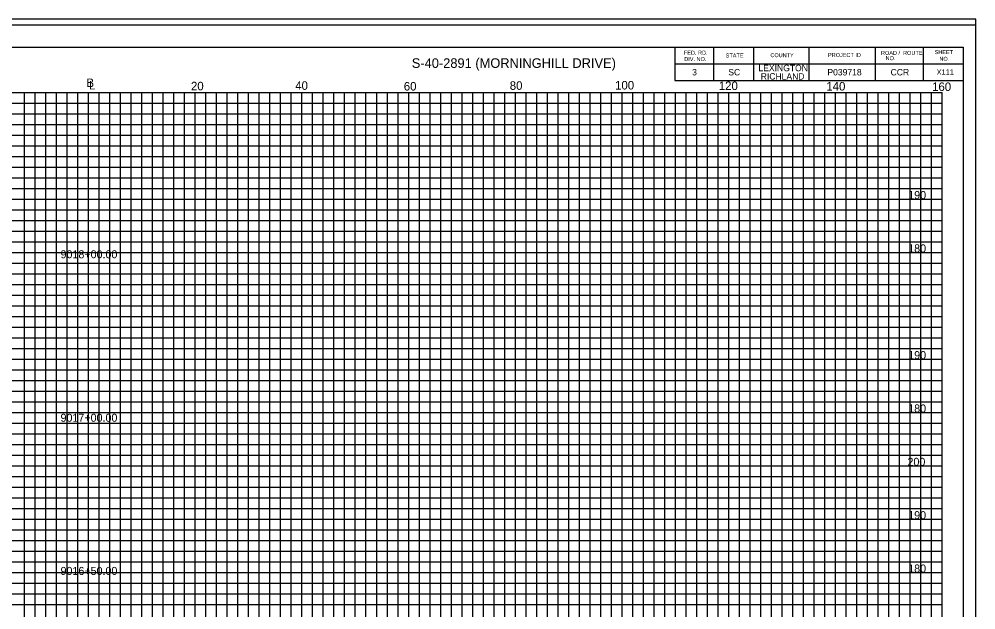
# Model space of a CAD drawing. Extents: x 967 to 1326, y 964 to 2584.
# Drawn here: x 1147 to 1326.3, y 2193 to 2303.7 of the extents above; entities that cross this region are included whole.
import ezdxf

# ---------------------------------------------------------------- set-up
doc = ezdxf.new("R2010")
doc.units = 0
for name, color, linetype in [('Default', 7, 'Continuous'), ('RD_GPK_XS_Cell', 7, 'Continuous'), ('RD_XS_ExGround', 7, 'Continuous'), ('RD_XS_ExPaveRet', 7, 'Continuous'), ('RD_XS_Misc_Line', 7, 'Continuous'), ('RD_XS_TX_Elev_EX', 7, 'Continuous')]:
    doc.layers.add(name, color=color, linetype=linetype)

msp = doc.modelspace()

# ---------------------------------------------------------------- linework, layer by layer
at = {"layer": 'RD_GPK_XS_Cell'}
for p, q in [((1000, 2290), (1320, 2290)), ((1150, 2120), (1150, 2290)), ((1160, 2120), (1160, 2290)), ((1170, 2120), (1170, 2290)), ((1180, 2120), (1180, 2290)), ((1190, 2120), (1190, 2290)), ((1200, 2120), (1200, 2290)), ((1210, 2120), (1210, 2290)), ((1220, 2120), (1220, 2290)), ((1230, 2120), (1230, 2290)), ((1240, 2120), (1240, 2290)), ((1250, 2120), (1250, 2290)), ((1260, 2120), (1260, 2290)), ((1270, 2120), (1270, 2290)), ((1280, 2120), (1280, 2290)), ((1290, 2120), (1290, 2290)), ((1300, 2120), (1300, 2290)), ((1310, 2120), (1310, 2290)), ((1320, 2120), (1320, 2290)), ((1000, 2280), (1320, 2280)), ((1000, 2270), (1320, 2270)), ((1000, 2260), (1320, 2260)), ((1000, 2250), (1320, 2250)), ((1000, 2240), (1320, 2240)), ((1000, 2230), (1320, 2230)), ((1000, 2220), (1320, 2220)), ((1000, 2210), (1320, 2210)), ((1000, 2200), (1320, 2200))]:
    msp.add_line(p, q, dxfattribs=at)
at = {"layer": 'RD_XS_ExGround'}
for p, q in [((1148, 2120), (1148, 2290)), ((1152, 2120), (1152, 2290)), ((1154, 2120), (1154, 2290)), ((1156, 2120), (1156, 2290)), ((1158, 2120), (1158, 2290)), ((1162, 2120), (1162, 2290)), ((1164, 2120), (1164, 2290)), ((1166, 2120), (1166, 2290)), ((1168, 2120), (1168, 2290)), ((1172, 2120), (1172, 2290)), ((1174, 2120), (1174, 2290)), ((1176, 2120), (1176, 2290)), ((1178, 2120), (1178, 2290)), ((1182, 2120), (1182, 2290)), ((1184, 2120), (1184, 2290)), ((1186, 2120), (1186, 2290)), ((1188, 2120), (1188, 2290)), ((1192, 2120), (1192, 2290)), ((1194, 2120), (1194, 2290)), ((1196, 2120), (1196, 2290)), ((1198, 2120), (1198, 2290)), ((1202, 2120), (1202, 2290)), ((1204, 2120), (1204, 2290)), ((1206, 2120), (1206, 2290)), ((1208, 2120), (1208, 2290)), ((1212, 2120), (1212, 2290)), ((1214, 2120), (1214, 2290)), ((1216, 2120), (1216, 2290)), ((1218, 2120), (1218, 2290)), ((1222, 2120), (1222, 2290)), ((1224, 2120), (1224, 2290)), ((1226, 2120), (1226, 2290)), ((1228, 2120), (1228, 2290)), ((1232, 2120), (1232, 2290)), ((1234, 2120), (1234, 2290)), ((1236, 2120), (1236, 2290)), ((1238, 2120), (1238, 2290)), ((1242, 2120), (1242, 2290)), ((1244, 2120), (1244, 2290)), ((1246, 2120), (1246, 2290)), ((1248, 2120), (1248, 2290)), ((1252, 2120), (1252, 2290)), ((1254, 2120), (1254, 2290)), ((1256, 2120), (1256, 2290)), ((1258, 2120), (1258, 2290)), ((1262, 2120), (1262, 2290)), ((1264, 2120), (1264, 2290)), ((1266, 2120), (1266, 2290)), ((1268, 2120), (1268, 2290)), ((1272, 2120), (1272, 2290)), ((1274, 2120), (1274, 2290)), ((1276, 2120), (1276, 2290)), ((1278, 2120), (1278, 2290)), ((1282, 2120), (1282, 2290)), ((1284, 2120), (1284, 2290)), ((1286, 2120), (1286, 2290)), ((1288, 2120), (1288, 2290)), ((1292, 2120), (1292, 2290)), ((1294, 2120), (1294, 2290)), ((1296, 2120), (1296, 2290)), ((1298, 2120), (1298, 2290)), ((1302, 2120), (1302, 2290)), ((1304, 2120), (1304, 2290)), ((1306, 2120), (1306, 2290)), ((1308, 2120), (1308, 2290)), ((1312, 2120), (1312, 2290)), ((1314, 2120), (1314, 2290)), ((1316, 2120), (1316, 2290)), ((1318, 2120), (1318, 2290)), ((1000, 2288), (1320, 2288)), ((1000, 2286), (1320, 2286)), ((1000, 2284), (1320, 2284)), ((1000, 2282), (1320, 2282)), ((1000, 2278), (1320, 2278)), ((1000, 2276), (1320, 2276)), ((1000, 2274), (1320, 2274)), ((1000, 2272), (1320, 2272)), ((1000, 2268), (1320, 2268)), ((1000, 2266), (1320, 2266)), ((1000, 2264), (1320, 2264)), ((1000, 2262), (1320, 2262)), ((1000, 2258), (1320, 2258)), ((1000, 2256), (1320, 2256)), ((1000, 2254), (1320, 2254)), ((1000, 2252), (1320, 2252)), ((1000, 2248), (1320, 2248)), ((1000, 2246), (1320, 2246)), ((1000, 2244), (1320, 2244)), ((1000, 2242), (1320, 2242)), ((1000, 2238), (1320, 2238)), ((1000, 2236), (1320, 2236)), ((1000, 2234), (1320, 2234)), ((1000, 2232), (1320, 2232)), ((1000, 2228), (1320, 2228)), ((1000, 2226), (1320, 2226)), ((1000, 2224), (1320, 2224)), ((1000, 2222), (1320, 2222)), ((1000, 2218), (1320, 2218)), ((1000, 2216), (1320, 2216)), ((1000, 2214), (1320, 2214)), ((1000, 2212), (1320, 2212)), ((1000, 2208), (1320, 2208)), ((1000, 2206), (1320, 2206)), ((1000, 2204), (1320, 2204)), ((1000, 2202), (1320, 2202)), ((1000, 2198), (1320, 2198)), ((1000, 2196), (1320, 2196)), ((1000, 2194), (1320, 2194))]:
    msp.add_line(p, q, dxfattribs=at)
at = {"layer": 'RD_XS_ExPaveRet'}
for points in [[(967.41, 2083.72), (1326.28, 2083.72), (1326.28, 2303.72), (967.41, 2303.72)], [(988.52, 2084.84), (1326.28, 2084.84), (1326.28, 2302.6), (988.52, 2302.6)]]:
    msp.add_lwpolyline(points, close=True, dxfattribs=at)
at = {"layer": 'RD_XS_TX_Elev_EX'}
for p, q in [((996.11, 2298.46), (1323.89, 2298.46)), ((1269.89, 2298.46), (1269.89, 2292.21)), ((1277.14, 2298.46), (1277.14, 2292.21)), ((1284.64, 2298.46), (1284.64, 2292.21)), ((1295, 2298.46), (1295, 2292.21)), ((1307.43, 2298.46), (1307.43, 2292.21)), ((1316.39, 2298.46), (1316.39, 2292.21)), ((1323.89, 2298.46), (1323.89, 2088.98)), ((1269.89, 2295.33), (1323.89, 2295.33)), ((1269.89, 2292.21), (1323.89, 2292.21))]:
    msp.add_line(p, q, dxfattribs=at)

# ---------------------------------------------------------------- texts
at = {"layer": 'Default'}
for s, height, p in [('X111', 1, (1318.94, 2293.3)), ('190', 1.5, (1313.61, 2270)), ('180', 1.5, (1313.61, 2260)), ('9018+00.00', 1.5, (1154.76, 2258.9)), ('190', 1.5, (1313.61, 2240)), ('180', 1.5, (1313.61, 2230)), ('9017+00.00', 1.5, (1154.76, 2228.26)), ('200', 1.5, (1313.47, 2220)), ('190', 1.5, (1313.61, 2210)), ('9016+50.00', 1.5, (1154.76, 2199.55)), ('180', 1.5, (1313.61, 2200))]:
    msp.add_text(s, height=height, dxfattribs=at).set_placement(p)
at = {"layer": 'RD_XS_Misc_Line'}
for s, height, p in [('FED. RD.', 0.75, (1271.58, 2297.05)), ('STATE', 0.75, (1279.41, 2296.53)), ('COUNTY', 0.75, (1287.78, 2296.59)), ('PROJECT ID', 0.75, (1298.58, 2296.63)), ('ROAD /  ROUTE', 0.75, (1308.51, 2297.01)), ('   NO.', 0.75, (1308.51, 2296.03)), ('SHEET', 0.75, (1318.56, 2297.16)), ('NO.', 0.75, (1319.45, 2295.91)), ('DIV. NO.', 0.75, (1271.64, 2295.86)), ('LEXINGTON', 1.2, (1285.54, 2293.96)), ('3', 1.2, (1273.12, 2293.17)), ('SC', 1.2, (1279.89, 2293.17)), ('RICHLAND', 1.2, (1285.97, 2292.39)), ('P039718', 1.2, (1298.46, 2293.17)), ('CCR', 1.2, (1310.31, 2293.17)), ('B', 1.6, (1159.61, 2290.99)), ('L', 1.6, (1160.12, 2290.54)), ('20', 1.6, (1179.2, 2290.38)), ('40', 1.6, (1198.74, 2290.47)), ('60', 1.6, (1219.08, 2290.33)), ('80', 1.6, (1238.94, 2290.47)), ('100', 1.6, (1258.67, 2290.53)), ('120', 1.6, (1278.11, 2290.43)), ('140', 1.6, (1298.26, 2290.34)), ('160', 1.6, (1318.08, 2290.25))]:
    msp.add_text(s, height=height, dxfattribs=at).set_placement(p)
msp.add_text('S-40-2891 (MORNINGHILL DRIVE)', height=1.8, rotation=0, dxfattribs=at).set_placement((1220.58, 2294.58))

doc.saveas('drawing.dxf')
